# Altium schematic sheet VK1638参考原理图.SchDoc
size A4
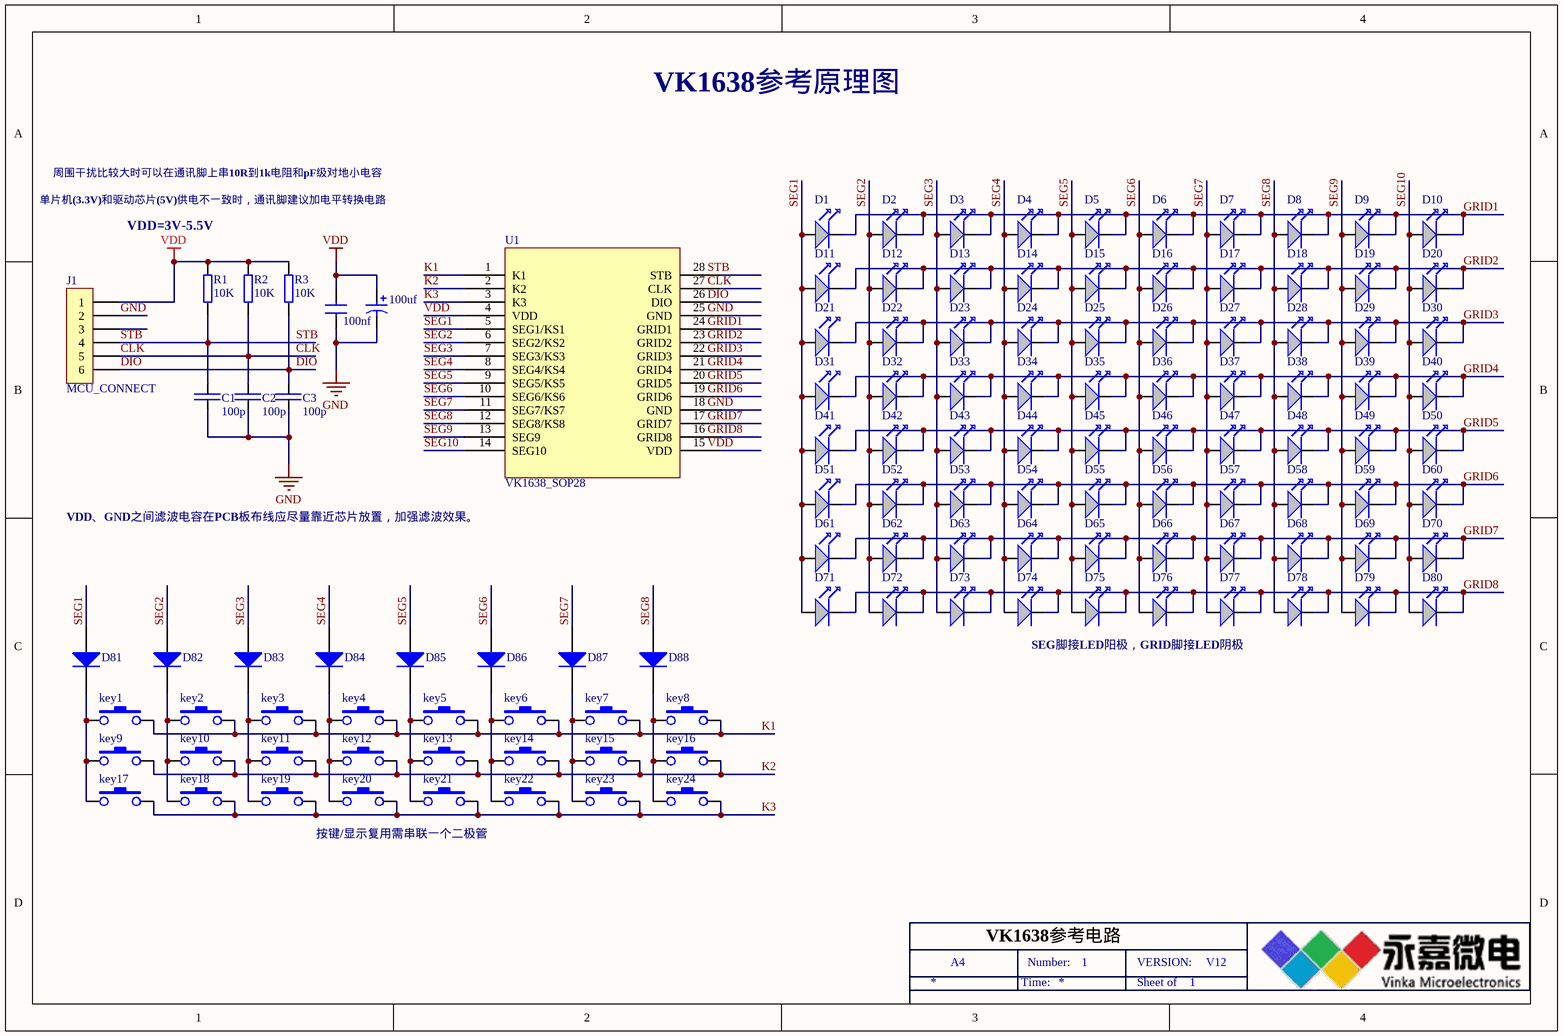
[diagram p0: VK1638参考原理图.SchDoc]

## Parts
100nf  CAP  (value not drawn)
100uf  CAP2  (value not drawn)
C1  100p  [C0603]
C2  100p  [C0603]
C3  100p  [C0603]
D1  (no value)  [1206-LED]
D2  (no value)  [1206-LED]
D3  (no value)  [1206-LED]
D4  (no value)  [1206-LED]
D5  (no value)  [1206-LED]
D6  (no value)  [1206-LED]
D7  (no value)  [1206-LED]
D8  (no value)  [1206-LED]
D9  (no value)  [1206-LED]
D10  (no value)  [1206-LED]
D11  (no value)  [1206-LED]
D12  (no value)  [1206-LED]
D13  (no value)  [1206-LED]
D14  (no value)  [1206-LED]
D15  (no value)  [1206-LED]
D16  (no value)  [1206-LED]
D17  (no value)  [1206-LED]
D18  (no value)  [1206-LED]
D19  (no value)  [1206-LED]
D20  (no value)  [1206-LED]
D21  (no value)  [1206-LED]
D22  (no value)  [1206-LED]
D23  (no value)  [1206-LED]
D24  (no value)  [1206-LED]
D25  (no value)  [1206-LED]
D26  (no value)  [1206-LED]
D27  (no value)  [1206-LED]
D28  (no value)  [1206-LED]
D29  (no value)  [1206-LED]
D30  (no value)  [1206-LED]
D31  (no value)  [1206-LED]
D32  (no value)  [1206-LED]
D33  (no value)  [1206-LED]
D34  (no value)  [1206-LED]
D35  (no value)  [1206-LED]
D36  (no value)  [1206-LED]
D37  (no value)  [1206-LED]
D38  (no value)  [1206-LED]
D39  (no value)  [1206-LED]
D40  (no value)  [1206-LED]
D41  (no value)  [1206-LED]
D42  (no value)  [1206-LED]
D43  (no value)  [1206-LED]
D44  (no value)  [1206-LED]
D45  (no value)  [1206-LED]
D46  (no value)  [1206-LED]
D47  (no value)  [1206-LED]
D48  (no value)  [1206-LED]
D49  (no value)  [1206-LED]
D50  (no value)  [1206-LED]
D51  (no value)  [1206-LED]
D52  (no value)  [1206-LED]
D53  (no value)  [1206-LED]
D54  (no value)  [1206-LED]
D55  (no value)  [1206-LED]
D56  (no value)  [1206-LED]
D57  (no value)  [1206-LED]
D58  (no value)  [1206-LED]
D59  (no value)  [1206-LED]
D60  (no value)  [1206-LED]
D61  (no value)  [1206-LED]
D62  (no value)  [1206-LED]
D63  (no value)  [1206-LED]
D64  (no value)  [1206-LED]
D65  (no value)  [1206-LED]
D66  (no value)  [1206-LED]
D67  (no value)  [1206-LED]
D68  (no value)  [1206-LED]
D69  (no value)  [1206-LED]
D70  (no value)  [1206-LED]
D71  (no value)  [1206-LED]
D72  (no value)  [1206-LED]
D73  (no value)  [1206-LED]
D74  (no value)  [1206-LED]
D75  (no value)  [1206-LED]
D76  (no value)  [1206-LED]
D77  (no value)  [1206-LED]
D78  (no value)  [1206-LED]
D79  (no value)  [1206-LED]
D80  (no value)  [1206-LED]
D81  Diode 1N4003  [DO-41]  (value not drawn)
D82  Diode 1N4003  [DO-41]  (value not drawn)
D83  Diode 1N4003  [DO-41]  (value not drawn)
D84  Diode 1N4003  [DO-41]  (value not drawn)
D85  Diode 1N4003  [DO-41]  (value not drawn)
D86  Diode 1N4003  [DO-41]  (value not drawn)
D87  Diode 1N4003  [DO-41]  (value not drawn)
D88  Diode 1N4003  [DO-41]  (value not drawn)
J1  MCU_CONNECT
key1  KEY  [AN12]  (value not drawn)
key2  KEY  [AN12]  (value not drawn)
key3  KEY  [AN12]  (value not drawn)
key4  KEY  [AN12]  (value not drawn)
key5  KEY  [AN12]  (value not drawn)
key6  KEY  [AN12]  (value not drawn)
key7  KEY  [AN12]  (value not drawn)
key8  KEY  [AN12]  (value not drawn)
key9  KEY  [AN12]  (value not drawn)
key10  KEY  [AN12]  (value not drawn)
key11  KEY  [AN12]  (value not drawn)
key12  KEY  [AN12]  (value not drawn)
key13  KEY  [AN12]  (value not drawn)
key14  KEY  [AN12]  (value not drawn)
key15  KEY  [AN12]  (value not drawn)
key16  KEY  [AN12]  (value not drawn)
key17  KEY  [AN12]  (value not drawn)
key18  KEY  [AN12]  (value not drawn)
key19  KEY  [AN12]  (value not drawn)
key20  KEY  [AN12]  (value not drawn)
key21  KEY  [AN12]  (value not drawn)
key22  KEY  [AN12]  (value not drawn)
key23  KEY  [AN12]  (value not drawn)
key24  KEY  [AN12]  (value not drawn)
R1  10K  [0603-R]
R2  10K  [0603-R]
R3  10K  [0603-R]
U1  VK1638_SOP28

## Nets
GND: 100nf.2 100uf.2 C1.2 C2.2 C3.2 J1.2
VDD: 100nf.1 100uf.1 J1.1 R1.1 R2.1 R3.1 U1.4(VDD)
CLK: C2.1 J1.5 R2.2
DIO: C3.1 J1.6 R3.2
GRID1: D1.2 D2.2 D3.2 D4.2 D5.2 D6.2 D7.2 D8.2 D9.2 D10.2
GRID2: D11.2 D12.2 D13.2 D14.2 D15.2 D16.2 D17.2 D18.2 D19.2 D20.2
GRID3: D21.2 D22.2 D23.2 D24.2 D25.2 D26.2 D27.2 D28.2 D29.2 D30.2
GRID4: D31.2 D32.2 D33.2 D34.2 D35.2 D36.2 D37.2 D38.2 D39.2 D40.2
GRID5: D41.2 D42.2 D43.2 D44.2 D45.2 D46.2 D47.2 D48.2 D49.2 D50.2
GRID6: D51.2 D52.2 D53.2 D54.2 D55.2 D56.2 D57.2 D58.2 D59.2 D60.2
GRID7: D61.2 D62.2 D63.2 D64.2 D65.2 D66.2 D67.2 D68.2 D69.2 D70.2
GRID8: D71.2 D72.2 D73.2 D74.2 D75.2 D76.2 D77.2 D78.2 D79.2 D80.2
K1: key1.2 key2.2 key3.2 key4.2 key5.2 key6.2 key7.2 key8.2 U1.1(K1)
K2: key9.2 key10.2 key11.2 key12.2 key13.2 key14.2 key15.2 key16.2 U1.2(K2)
K3: key17.2 key18.2 key19.2 key20.2 key21.2 key22.2 key23.2 key24.2 U1.3(K3)
SEG1: D1.1 D11.1 D21.1 D31.1 D41.1 D51.1 D61.1 D71.1 D81.1(A) U1.5(SEG1/KS1)
SEG2: D2.1 D12.1 D22.1 D32.1 D42.1 D52.1 D62.1 D72.1 D82.1(A) U1.6(SEG2/KS2)
SEG3: D3.1 D13.1 D23.1 D33.1 D43.1 D53.1 D63.1 D73.1 D83.1(A) U1.7(SEG3/KS3)
SEG4: D4.1 D14.1 D24.1 D34.1 D44.1 D54.1 D64.1 D74.1 D84.1(A) U1.8(SEG4/KS4)
SEG5: D5.1 D15.1 D25.1 D35.1 D45.1 D55.1 D65.1 D75.1 D85.1(A) U1.9(SEG5/KS5)
SEG6: D6.1 D16.1 D26.1 D36.1 D46.1 D56.1 D66.1 D76.1 D86.1(A) U1.10(SEG6/KS6)
SEG7: D7.1 D17.1 D27.1 D37.1 D47.1 D57.1 D67.1 D77.1 D87.1(A) U1.11(SEG7/KS7)
SEG8: D8.1 D18.1 D28.1 D38.1 D48.1 D58.1 D68.1 D78.1 D88.1(A) U1.12(SEG8/KS8)
SEG9: D9.1 D19.1 D29.1 D39.1 D49.1 D59.1 D69.1 D79.1 U1.13(SEG9)
SEG10: D10.1 D20.1 D30.1 D40.1 D50.1 D60.1 D70.1 D80.1 U1.14(SEG10)
STB: C1.1 J1.4 R1.2
NetD81_2: D81.2(K) key1.1 key9.1 key17.1
NetD82_2: D82.2(K) key2.1 key10.1 key18.1
NetD83_2: D83.2(K) key3.1 key11.1 key19.1
NetD84_2: D84.2(K) key4.1 key12.1 key20.1
NetD85_2: D85.2(K) key5.1 key13.1 key21.1
NetD86_2: D86.2(K) key6.1 key14.1 key22.1
NetD87_2: D87.2(K) key7.1 key15.1 key23.1
NetD88_2: D88.2(K) key8.1 key16.1 key24.1

Not connected (* = marked no-connect by the designer): J1 3; U1 15(VDD) 16(GRID8) 17(GRID7) 18(GND) 19(GRID6) 20(GRID5) 21(GRID4) 22(GRID3) 23(GRID2) 24(GRID1) 25(GND) 26(DIO) 27(CLK) 28(STB)

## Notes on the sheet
- VK1638参考原理图
- 周围干扰比较大时可以在通讯脚上串10R到1k电阻和pF级对地小电容
- 单片机(3.3V)和驱动芯片(5V)供电不一致时，通讯脚建议加电平转换电路
- VDD=3V-5.5V
- VDD、GND之间滤波电容在PCB板布线应尽量靠近芯片放置，加强滤波效果。
- SEG脚接LED阳极，GRID脚接LED阴极
- 按键/显示复用需串联一个二极管
- A4
- VK1638参考电路
- Time:
- Number:
- 1
- Sheet of
- VERSION:
- V12
- Labels drawn without touching a wire or pin: CLK, DIO, GND, GRID1, GRID2, GRID3, GRID4, GRID5, GRID6, GRID7, GRID8, STB, VDD

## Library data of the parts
100nf = CAP: Capacitor
100uf = CAP2: Bi-Polar Capacitor
C1-C3 = CAP: 分类: 电容; 参数: 20%,50V,X5R
D1-D80 = LED: Text Field1: 30; Text Field2: 20
D81-D88 = Diode 1N4003: 1 Amp General Purpose Rectifier
J1 = CON6: Connector
R1-R3 = RES: Resistor
U1 = VK1638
